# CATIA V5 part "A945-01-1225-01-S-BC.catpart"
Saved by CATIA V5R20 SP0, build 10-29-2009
Part number: A945-01-1225-01-S-BC
Source: Unknown
Property "ARTICLENO": "A945-01-1225-01-S-BC"
Property "B": "125.000"
Property "BOMINFO": "A945-01-1225-01-S-BC"
Property "CODE": "A945-01-1225-01-S-BC"
Property "D1": "26.000"
Property "D2": "17.500"
Property "D5": "20.000"
Property "D6": "16.000"
Property "H": "57.000"
Property "H1": "44.000"
Property "H2": "60.000"
Property "H3": "28.000"
Property "L1": "250.000"
Property "L2": "25.000"
Property "L3": "100.000"
Property "L4": "100.000"
Property "L5": "55.000"
Property "L6": "145.000"
Property "LINA": "A945-01-1225-01-S-BC"
Property "N": "7.000"
Property "NB": "A945-01-1225-01-S-BC"
Property "NBSYN": " $CODE."
Property "NN": "A945-01"
Property "NT": "v driver sets replaceable inserts pisitive return"
Property "SUPPLIER": "CF"
Property "Z": "85.000"
Bounding box of the stored display mesh (mm): x -669.473 to -511.473, y 748.188 to 833.188, z 0 to 250
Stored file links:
  C:\Users\Utente\Desktop\3D files A945-01\A945-01-1225-01-S-BC.catpart
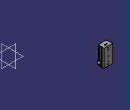
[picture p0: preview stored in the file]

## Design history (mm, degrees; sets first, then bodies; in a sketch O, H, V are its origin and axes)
Body1 "Geometry.1" (main body)
  Solid1 "A945-01-1225-01-S-BC.catpart": solid without history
